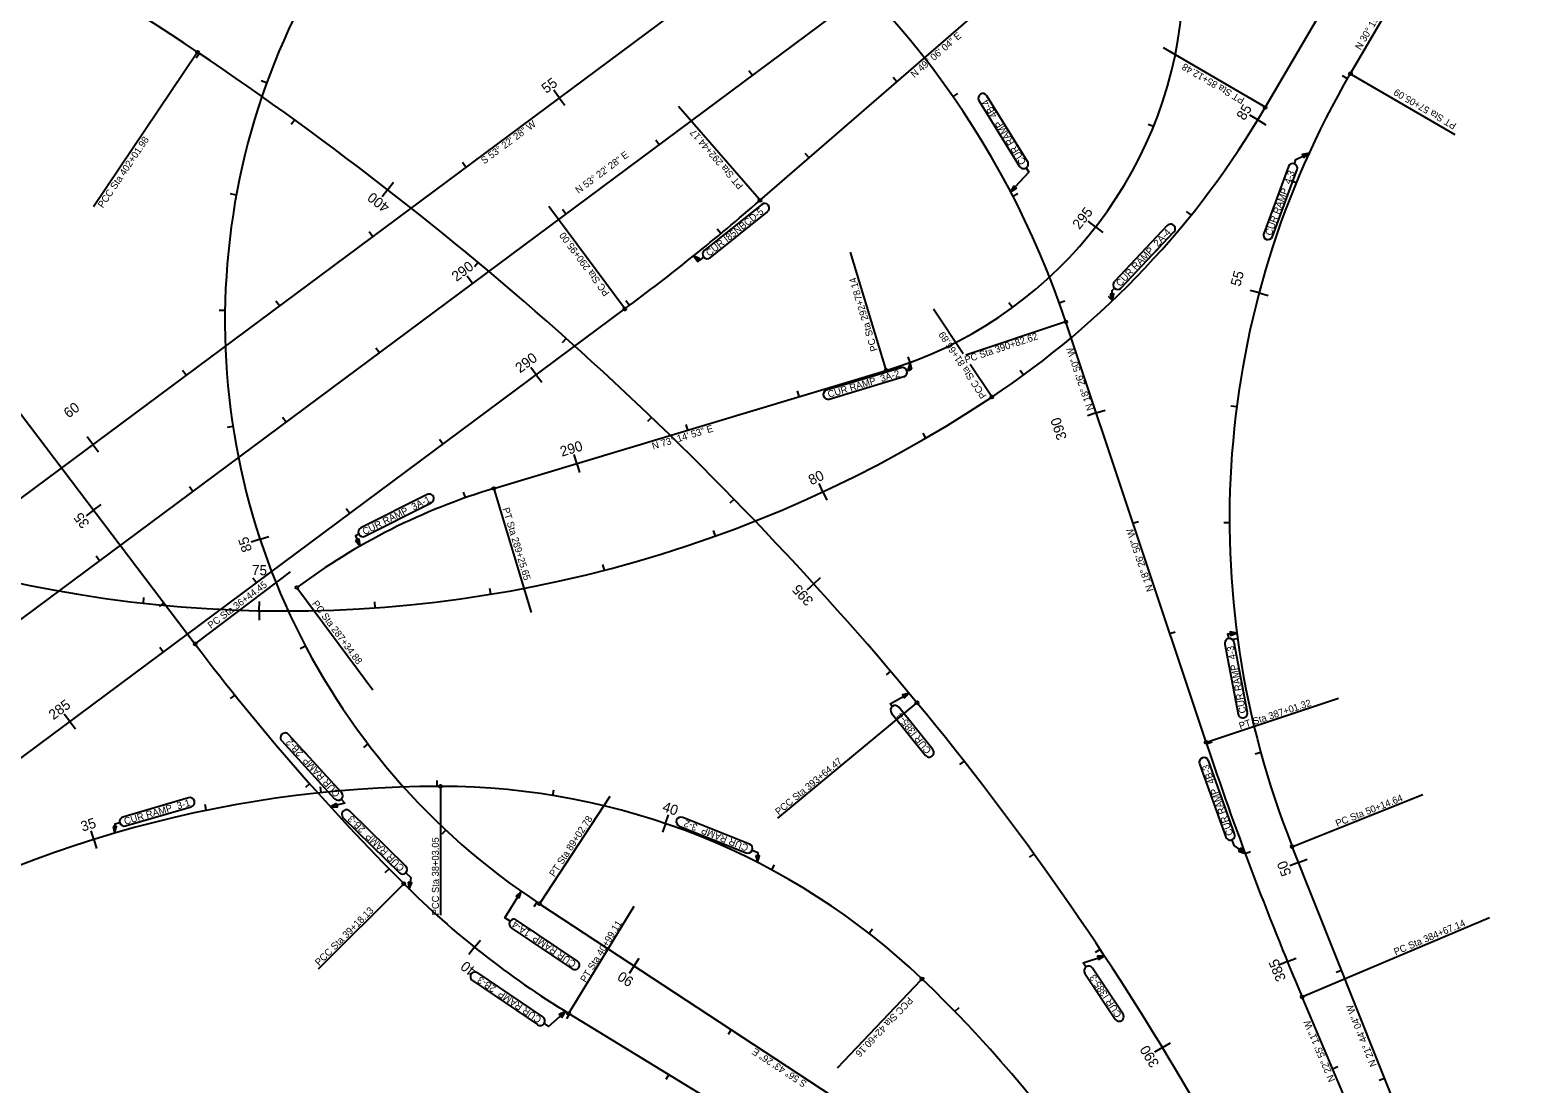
# Model space of a CAD drawing. Extents: x 1603540 to 1622629, y 1083934 to 1103503.
# Drawn here: x 1610388 to 1611685, y 1093197 to 1094104 of the extents above; entities that cross this region are included whole.
import ezdxf

# ---------------------------------------------------------------- set-up
doc = ezdxf.new("R2010")
doc.units = 0
for name, color, linetype in [('RD_EX_BldgChurch', 7, 'Continuous'), ('RD_EX_Fence_ChLk', 7, 'Continuous'), ('RD_EX_H2O', 7, 'Continuous'), ('RD_EX_Misc', 7, 'Continuous'), ('RD_HC_CL', 7, 'Continuous'), ('RD_PG_GR', 7, 'Continuous')]:
    doc.layers.add(name, color=color, linetype=linetype)

msp = doc.modelspace()

# ---------------------------------------------------------------- linework, layer by layer
at = {"layer": 'RD_EX_BldgChurch'}
for p, q in [((1610531.3, 1094083.8), (1610442.6, 1093951.6)), ((1611449.7, 1094037.9), (1611363.1, 1094088.5)), ((1611525, 1094065.7), (1611613.8, 1094013.8)), ((1611015.2, 1093958.2), (1610946, 1094038.1)), ((1610899, 1093864.9), (1610834.3, 1093951.9)), ((1611124.2, 1093812.2), (1611094, 1093912.6)), ((1611190.8, 1093825.3), (1611165.2, 1093863.8)), ((1611278, 1093852.4), (1611193.1, 1093824)), ((1611214.9, 1093789.1), (1611196.9, 1093816.1)), ((1610787.4, 1093708.2), (1610819.2, 1093602.6)), ((1610530.8, 1093576.3), (1610612, 1093637.8)), ((1610618.2, 1093623.2), (1610682.9, 1093536.2)), ((1611401, 1093491.4), (1611513.8, 1093529.1)), ((1611150.1, 1093524.3), (1611031.2, 1093425.7)), ((1610741.2, 1093451.8), (1610741.2, 1093342.2)), ((1610827, 1093353.1), (1610887.2, 1093444.7)), ((1611475.2, 1093401.7), (1611586.3, 1093446)), ((1610636.1, 1093296), (1610708.6, 1093368.5)), ((1610852.1, 1093258.8), (1610907.6, 1093350)), ((1611483.6, 1093272.5), (1611643.7, 1093340.2)), ((1611154.5, 1093286.5), (1611082.3, 1093210.7))]:
    msp.add_line(p, q, dxfattribs=at)
for centre in [(1610532, 1094084.8), (1611524, 1094066.3), (1611450.7, 1094037.2), (1611016, 1093957.2), (1610899.7, 1093863.9), (1611279.1, 1093852.8), (1611124.6, 1093811), (1611215.6, 1093788.1), (1610787.1, 1093709.4), (1610617.5, 1093624.2), (1610529.9, 1093575.5), (1611151.1, 1093525.1), (1611399.8, 1093491), (1610741.2, 1093453.1), (1611474, 1093401.3), (1610709.5, 1093369.4), (1610826.4, 1093352.1), (1611155.4, 1093287.4), (1611482.5, 1093272), (1610851.4, 1093257.7)]:
    msp.add_circle(centre, 1.25, dxfattribs=at)
at = {"layer": 'RD_EX_H2O'}
for p, q in [((1610533.6, 1094083.7), (1610530.9, 1094079.6)), ((1610591.5, 1094058.3), (1610586.8, 1094060)), ((1611009.5, 1094064.8), (1611006.5, 1094068.8)), ((1611133.8, 1094059.3), (1611130.5, 1094063)), ((1611521.4, 1094061.9), (1611517.1, 1094064.4)), ((1610843.2, 1094045.5), (1610838.5, 1094052)), ((1610843.2, 1094045.5), (1610848, 1094039.1)), ((1611182, 1094046.4), (1611186.1, 1094049.2)), ((1610615.7, 1094026.5), (1610612.7, 1094022.5)), ((1611354.6, 1094020.8), (1611349.9, 1094022.6)), ((1611444.4, 1094026.5), (1611437.5, 1094030.6)), ((1611444.4, 1094026.5), (1611451.2, 1094022.3)), ((1610929.2, 1094005.1), (1610926.3, 1094009.1)), ((1611058.2, 1093993.8), (1611054.9, 1093997.6)), ((1610763, 1093985.9), (1610760, 1093989.9)), ((1610695.7, 1093966.5), (1610690.8, 1093960.2)), ((1610695.7, 1093966.5), (1610700.6, 1093972.8)), ((1611477.3, 1093972.3), (1611472.7, 1093974.2)), ((1610565.4, 1093961.8), (1610560.5, 1093962.8)), ((1611233.6, 1093960.8), (1611238, 1093963.1)), ((1610849, 1093945.5), (1610846, 1093949.5)), ((1611387, 1093944.7), (1611383.1, 1093947.8)), ((1610682.7, 1093926.2), (1610679.7, 1093930.2)), ((1610982.3, 1093928.7), (1610979.1, 1093932.5)), ((1611304.8, 1093934.4), (1611298.5, 1093939.3)), ((1611304.8, 1093934.4), (1611311.1, 1093929.5)), ((1610773.6, 1093903.8), (1610770.4, 1093900)), ((1610768.7, 1093885.8), (1610764, 1093892.2)), ((1611445.4, 1093877.6), (1611437.7, 1093879.6)), ((1611445.4, 1093877.6), (1611453.2, 1093875.5)), ((1610602.5, 1093866.6), (1610599.5, 1093870.6)), ((1610903.7, 1093866.9), (1610900.7, 1093870.9)), ((1611233.2, 1093865), (1611230.2, 1093869.1)), ((1611273.5, 1093869.2), (1611278.2, 1093870.9)), ((1611319.4, 1093871.1), (1611315.9, 1093874.7)), ((1610555.6, 1093862.4), (1610550.6, 1093862.5)), ((1610849.3, 1093838.5), (1610845.9, 1093834.8)), ((1610688.5, 1093826.1), (1610685.5, 1093830.2)), ((1610522.2, 1093806.9), (1610519.2, 1093810.9)), ((1610823.5, 1093807.2), (1610818.7, 1093813.6)), ((1611145.3, 1093817.9), (1611143.6, 1093822.6)), ((1611242.7, 1093807), (1611239.8, 1093811)), ((1610823.5, 1093807.2), (1610828.2, 1093800.8)), ((1611049.8, 1093788.5), (1611048.3, 1093793.3)), ((1611305.3, 1093774.4), (1611297.7, 1093771.8)), ((1611305.3, 1093774.4), (1611312.9, 1093776.9)), ((1611426.2, 1093779.5), (1611421.2, 1093780.1)), ((1610562.5, 1093762.8), (1610557.5, 1093762)), ((1610608.2, 1093766.5), (1610605.2, 1093770.5)), ((1610922.7, 1093770.6), (1610919.2, 1093767)), ((1610954, 1093759.7), (1610952.6, 1093764.5)), ((1610442, 1093747.3), (1610437.2, 1093753.7)), ((1610442, 1093747.3), (1610446.7, 1093740.8)), ((1610743.2, 1093747.5), (1610740.2, 1093751.5)), ((1611158.8, 1093752.7), (1611156.3, 1093757.1)), ((1610858.3, 1093730.8), (1610856, 1093738.5)), ((1610858.3, 1093730.8), (1610860.6, 1093723.2)), ((1610528, 1093706.8), (1610525, 1093710.8)), ((1611070.1, 1093706.5), (1611066.8, 1093713.8)), ((1610442.6, 1093690.7), (1610449, 1093695.5)), ((1610762.7, 1093701.5), (1610761, 1093706.2)), ((1610993.7, 1093700.2), (1610990.1, 1093696.7)), ((1611070.1, 1093706.5), (1611073.5, 1093699.3)), ((1610442.6, 1093690.7), (1610436.2, 1093685.8)), ((1610663, 1093687.9), (1610660, 1093691.9)), ((1611336.9, 1093679.5), (1611341.7, 1093681.1)), ((1610585.8, 1093665.7), (1610593.4, 1093668.2)), ((1610977.7, 1093668.5), (1610976, 1093673.2)), ((1611420, 1093679.8), (1611415, 1093679.7)), ((1610585.8, 1093665.7), (1610578.2, 1093663.2)), ((1610671.9, 1093659.8), (1610669.4, 1093664.2)), ((1610447.7, 1093647.2), (1610444.7, 1093651.2)), ((1610882.1, 1093639.1), (1610880.9, 1093643.9)), ((1610582.7, 1093628.2), (1610579.7, 1093632.2)), ((1611062.2, 1093627.4), (1611068.2, 1093632.8)), ((1610784.3, 1093618.5), (1610783.5, 1093623.4)), ((1611062.2, 1093627.4), (1611056.3, 1093622)), ((1610485.4, 1093610.7), (1610485.9, 1093615.6)), ((1610503, 1093611), (1610499, 1093607.9)), ((1610585.1, 1093604.2), (1610585, 1093596.2)), ((1610585.1, 1093604.2), (1610585.3, 1093612.2)), ((1610685, 1093606.8), (1610684.7, 1093611.8)), ((1611368.6, 1093584.6), (1611373.3, 1093586.2)), ((1611427, 1093580.1), (1611422, 1093579.4)), ((1610502.5, 1093568.6), (1610499.5, 1093572.6)), ((1610624.9, 1093573.7), (1610620.4, 1093571.4)), ((1611128.3, 1093552.3), (1611124.5, 1093549.1)), ((1610564, 1093531.7), (1610560.1, 1093528.6)), ((1610422.2, 1093508.9), (1610417.4, 1093515.3)), ((1610422.2, 1093508.9), (1610427, 1093502.5)), ((1610678.7, 1093489.6), (1610674.7, 1093486.5)), ((1611400.2, 1093489.8), (1611405, 1093491.4)), ((1611191.6, 1093474.9), (1611187.6, 1093471.8)), ((1611447, 1093482.2), (1611442.1, 1093480.8)), ((1610628.5, 1093455.3), (1610624.8, 1093452)), ((1610638.3, 1093447.7), (1610637.8, 1093452.7)), ((1610738.1, 1093453.1), (1610738.1, 1093458.1)), ((1610837.7, 1093445.3), (1610838.5, 1093450.2)), ((1610539.5, 1093432.5), (1610538.5, 1093437.4)), ((1610934.6, 1093421.1), (1610937.2, 1093428.7)), ((1610442.7, 1093407.4), (1610440.4, 1093415)), ((1610745.7, 1093415.5), (1610742.3, 1093411.9)), ((1610934.6, 1093421.1), (1610932, 1093413.6)), ((1610442.7, 1093407.4), (1610445.1, 1093399.8)), ((1611433.5, 1093395.5), (1611438.2, 1093397.2)), ((1611026.2, 1093381.2), (1611028.5, 1093385.6)), ((1611251.8, 1093395.1), (1611247.7, 1093392.1)), ((1611479.5, 1093387.7), (1611472, 1093384.7)), ((1611479.5, 1093387.7), (1611486.9, 1093390.6)), ((1610696.8, 1093382.2), (1610693.2, 1093378.7)), ((1610824, 1093353.6), (1610821.3, 1093349.4)), ((1610770.4, 1093314.7), (1610775.4, 1093320.9)), ((1611109.8, 1093326.7), (1611112.9, 1093330.6)), ((1610770.4, 1093314.7), (1610765.4, 1093308.5)), ((1610907.6, 1093298.7), (1610912, 1093305.4)), ((1611308.7, 1093312.9), (1611304.5, 1093310.1)), ((1611469.9, 1093302.3), (1611477.3, 1093305.4)), ((1610907.6, 1093298.7), (1610903.3, 1093292)), ((1611469.9, 1093302.3), (1611462.5, 1093299.3)), ((1611516.5, 1093294.8), (1611511.9, 1093292.9)), ((1610852.2, 1093257.3), (1610849.6, 1093253)), ((1611183.7, 1093259.4), (1611187.3, 1093262.9)), ((1610991.2, 1093243.8), (1610988.5, 1093239.7)), ((1611362.3, 1093228.5), (1611355.5, 1093224.3)), ((1611362.3, 1093228.5), (1611369.2, 1093232.6)), ((1610937.6, 1093205.2), (1610935, 1093201)), ((1611508.6, 1093210.2), (1611513.2, 1093212.1)), ((1611553.5, 1093201.9), (1611548.9, 1093200))]:
    msp.add_line(p, q, dxfattribs=at)
at = {"layer": 'RD_HC_CL'}
for p, q in [((1609261, 1092765), (1614429, 1096606.7)), ((1611290.5, 1094378), (1610191.6, 1093561.1)), ((1611450.7, 1094037.2), (1611579.5, 1094257.5)), ((1611016, 1093957.2), (1611326.7, 1094226.4)), ((1611524, 1094066.3), (1611621.4, 1094233)), ((1610217, 1093988.4), (1610529.9, 1093575.5)), ((1609780.9, 1093032.2), (1610899.7, 1093863.9)), ((1611399.8, 1093491), (1611279.1, 1093852.8)), ((1610787.1, 1093709.4), (1611124.6, 1093811)), ((1611582.6, 1093128.9), (1611474, 1093401.3)), ((1610826.4, 1093352.1), (1611228.3, 1093088.3)), ((1611548.7, 1093115.4), (1611482.5, 1093272)), ((1610851.4, 1093257.7), (1611167.1, 1093065.3))]:
    msp.add_line(p, q, dxfattribs=at)
for centre, radius, start, end in [((1611155.6, 1093853.7), 600, 109.8521, 236.724), ((1609417.4, 1092424.2), 2000, 56.1301, 81.5065), ((1610558.2, 1093612.3), 760, 18.4471, 165.9491), ((1611020.8, 1094155.7), 360, 286.7519, 354.6184), ((1608910.9, 1091669.6), 2908.8, 39.6334, 56.1301), ((1612180, 1093682.7), 760, 149.6819, 201.7343), ((1610794.7, 1094420.9), 760, 303.6278, 329.6819), ((1609706.6, 1095469), 2000, 306.6256, 310.899), ((1610606.4, 1094704), 1100, 229.4294, 303.6278), ((1610945.6, 1093182.8), 550, 106.7519, 126.6256), ((1612124, 1094783.4), 2000, 217.1508, 224.9911), ((1609225.7, 1091930.4), 2500, 20.7167, 39.6334), ((1614245.6, 1094440.3), 3000, 198.4471, 202.9196), ((1610741.6, 1092453.1), 1000, 90.0249, 122.6256), ((1610741.4, 1092853.1), 600, 46.3737, 90.0249), ((1611247, 1093906.7), 760, 224.9911, 238.635), ((1610396.4, 1092491.2), 1100, 23.0073, 46.3737)]:
    msp.add_arc(centre, radius, start, end, dxfattribs=at)
at = {"layer": 'RD_PG_GR'}
for p, q in [((1611246.2, 1093990.7), (1611211.2, 1094047.3)), ((1611204.4, 1094043.1), (1611239.4, 1093986.5)), ((1611470.7, 1093986.4), (1611449.4, 1093928.9)), ((1611456.9, 1093926.1), (1611478.2, 1093983.7)), ((1611017.5, 1093953.8), (1610968.1, 1093914.1)), ((1610973.1, 1093907.9), (1611022.5, 1093947.5)), ((1611366.4, 1093935.6), (1611320.9, 1093887.4)), ((1611326.7, 1093881.9), (1611372.2, 1093930.1)), ((1611137.4, 1093813.3), (1611073.3, 1093794)), ((1611075.6, 1093786.3), (1611139.7, 1093805.6)), ((1610729.6, 1093704.2), (1610672.5, 1093675.5)), ((1610676.1, 1093668.3), (1610733.2, 1093697)), ((1611416.1, 1093575.5), (1611427.5, 1093515.2)), ((1611435.4, 1093516.7), (1611424, 1093577)), ((1611129.2, 1093516.2), (1611158.4, 1093479.7)), ((1611164.6, 1093484.7), (1611135.4, 1093521.2)), ((1610604.5, 1093492.4), (1610650, 1093442.4)), ((1610655.9, 1093447.8), (1610610.4, 1093497.8)), ((1611424.4, 1093412.2), (1611401.8, 1093475.3)), ((1611394.3, 1093472.6), (1611416.9, 1093409.5)), ((1610524.4, 1093443.3), (1610467.9, 1093426.7)), ((1610470.1, 1093419.1), (1610526.7, 1093435.6)), ((1610657.4, 1093426.1), (1610705.7, 1093378.7)), ((1610711.3, 1093384.4), (1610663, 1093431.8)), ((1611007, 1093403.4), (1610949.5, 1093426.4)), ((1610946.5, 1093419), (1611004.1, 1093396)), ((1610802, 1093331.5), (1610854.4, 1093296)), ((1610858.9, 1093302.7), (1610806.5, 1093338.1)), ((1610829.2, 1093254.7), (1610773.1, 1093292.6)), ((1611295.4, 1093292.2), (1611321.7, 1093252.8)), ((1611328.4, 1093257.2), (1611302.1, 1093296.7)), ((1610768.6, 1093286), (1610824.7, 1093248.1))]:
    msp.add_line(p, q, dxfattribs=at)
for points in [[(1611475.8, 1093988.8), (1611477.1, 1093992.3), (1611488.4, 1093997.8)], [(1611244.9, 1093985.2), (1611247.2, 1093981.5), (1611231.6, 1093964.5)], [(1610967.4, 1093908.5), (1610963.8, 1093905.5), (1610958.7, 1093909.5)], [(1611321.1, 1093881.7), (1611318.7, 1093879.3), (1611319.4, 1093871.1)], [(1611142.4, 1093810.6), (1611145.1, 1093811.4), (1611145.3, 1093817.9)], [(1610670.7, 1093670.1), (1610667.9, 1093668.7), (1610671.9, 1093659.8)], [(1611419.3, 1093580.2), (1611418.5, 1093584.3), (1611426.4, 1093584.8)], [(1611129.8, 1093521.8), (1611127.9, 1093524.1), (1611144.5, 1093533.2)], [(1610655.7, 1093442.2), (1610658.8, 1093438.8), (1610646.5, 1093435.6)], [(1610465.2, 1093421.8), (1610461, 1093420.5), (1610460.5, 1093412.8)], [(1611009.3, 1093398.2), (1611014.2, 1093396.3), (1611013.8, 1093387.7)], [(1611422, 1093407.1), (1611423.7, 1093402.2), (1611433.5, 1093395.5)], [(1610711.3, 1093378.7), (1610715.5, 1093374.7), (1610714.1, 1093364.6)], [(1610801, 1093337), (1610796.5, 1093340.1), (1610810.5, 1093362.7)], [(1611296.5, 1093297.8), (1611294.2, 1093301.3), (1611312.3, 1093307.4)], [(1610830.2, 1093249.1), (1610834.1, 1093246.5), (1610848.7, 1093259.4)]]:
    msp.add_lwpolyline(points, dxfattribs=at)
for points in [[(1611483.9, 1093993.9), (1611488.4, 1093997.8), (1611482.5, 1093996.7)], [(1611234.4, 1093969.8), (1611231.6, 1093964.5), (1611236.7, 1093967.7)], [(1610964.3, 1093907.1), (1610958.7, 1093909.5), (1610962.4, 1093904.7)], [(1611317.4, 1093876.7), (1611319.4, 1093871.1), (1611320.5, 1093877)], [(1611146.7, 1093812.1), (1611145.3, 1093817.9), (1611143.6, 1093812.2)], [(1610668.1, 1093664.5), (1610671.9, 1093659.8), (1610671, 1093665.8)], [(1611420.7, 1093582.9), (1611426.4, 1093584.8), (1611420.5, 1093586)], [(1611140.2, 1093529.1), (1611144.5, 1093533.2), (1611138.7, 1093531.8)], [(1610651.7, 1093438.5), (1610646.5, 1093435.6), (1610652.5, 1093435.5)], [(1610459.3, 1093418.6), (1610460.5, 1093412.8), (1610462.4, 1093418.5)], [(1611427.8, 1093397.5), (1611433.5, 1093395.5), (1611429.6, 1093400)], [(1611012.5, 1093393.5), (1611013.8, 1093387.7), (1611015.6, 1093393.4)], [(1610713.4, 1093370.6), (1610714.1, 1093364.6), (1610716.4, 1093370.2)], [(1610808.8, 1093357), (1610810.5, 1093362.7), (1610806.1, 1093358.6)], [(1611307.3, 1093304.1), (1611312.3, 1093307.4), (1611306.3, 1093307)], [(1610845.4, 1093254.4), (1610848.7, 1093259.4), (1610843.3, 1093256.7)]]:
    msp.add_lwpolyline(points, close=True, dxfattribs=at)
for centre, start, end in [((1611207.8, 1094045.2), 31.726, 211.726), ((1611242.8, 1093988.6), 211.726, 31.726), ((1611474.4, 1093985), 339.726, 159.726), ((1611020, 1093950.7), 308.7623, 128.7623), ((1611369.3, 1093932.8), 316.6549, 136.6549), ((1611453.1, 1093927.5), 159.726, 339.726), ((1610970.6, 1093911), 128.7623, 308.7623), ((1611323.8, 1093884.6), 136.6549, 316.6549), ((1611138.6, 1093809.4), 286.726, 106.726), ((1611074.4, 1093790.2), 106.726, 286.726), ((1610731.4, 1093700.6), 296.6888, 116.6888), ((1610674.3, 1093671.9), 116.6888, 296.6888), ((1611420, 1093576.3), 10.6915, 190.6915), ((1611132.3, 1093518.7), 38.6915, 218.6915), ((1611431.4, 1093516), 190.6915, 10.6915), ((1610607.4, 1093495.1), 42.3719, 222.3719), ((1611161.5, 1093482.2), 218.6915, 38.6915), ((1611398, 1093474), 19.6915, 199.6915), ((1610653, 1093445.1), 222.3719, 42.3719), ((1610525.5, 1093439.5), 286.3252, 106.3252), ((1610469, 1093422.9), 106.3252, 286.3252), ((1610660.2, 1093429), 45.4891, 225.4891), ((1610948, 1093422.7), 68.1993, 248.1993), ((1611420.6, 1093410.9), 199.6915, 19.6915), ((1611005.5, 1093399.7), 248.1993, 68.1993), ((1610708.5, 1093381.5), 225.4891, 45.4891), ((1610804.3, 1093334.8), 55.9145, 235.9145), ((1610770.8, 1093289.3), 55.9145, 235.9145), ((1610856.7, 1093299.4), 235.9145, 55.9145), ((1611298.8, 1093294.4), 33.6915, 213.6915), ((1610826.9, 1093251.4), 235.9145, 55.9145), ((1611325, 1093255), 213.6915, 33.6915)]:
    msp.add_arc(centre, 4, start, end, dxfattribs=at)

# ---------------------------------------------------------------- texts
at = {"layer": 'RD_EX_BldgChurch'}
for s, rotation, p in [('PT Sta 85+12.48', 149.6819, (1611433.5, 1094045)), ('PT Sta 57+05.09', 149.6819, (1611615.8, 1094023.1)), ('PCC Sta 402+01.98', 56.1301, (1610450.7, 1093950.2)), ('PT Sta 292+44.17', 130.899, (1611002.2, 1093970.1)), ('PC Sta 290+95.00', 126.6256, (1610886.9, 1093877.7)), ('PC Sta 292+78.14', 106.7519, (1611117.3, 1093828.4)), ('PCC Sta 81+66.89', 123.6278, (1611211.3, 1093789.2)), ('PC Sta 390+82.62', 18.4471, (1611193.2, 1093817.1)), ('PT Sta 289+25.65', 286.7519, (1610794.4, 1093692)), ('PC Sta 36+44.45', 37.1508, (1610543.6, 1093588.4)), ('PC Sta 287+34.88', 306.6256, (1610630.3, 1093610.3)), ('PT Sta 387+01.32', 18.4471, (1611429.3, 1093502)), ('PCC Sta 393+64.47', 39.6334, (1611032.1, 1093428.1)), ('PC Sta 50+14.64', 21.7343, (1611512.7, 1093418.2)), ('PT Sta 89+02.78', 56.724, (1610839.1, 1093374.8)), ('PCC Sta 38+03.05', 90.0249, (1610739.7, 1093342.2)), ('PCC Sta 39+18.13', 44.9911, (1610636.6, 1093298.3)), ('PT Sta 40+99.11', 58.635, (1610866, 1093283.9)), ('PC Sta 384+67.14', 22.9196, (1611562.9, 1093307.7)), ('PCC Sta 42+60.16', 226.3737, (1611143.9, 1093272.4))]:
    msp.add_text(s, height=6, rotation=rotation, dxfattribs=at).set_placement(p)
at = {"layer": 'RD_EX_Fence_ChLk'}
for s, rotation, p in [('N 30%%d 19\' 05" E', 59.6819, (1611532.8, 1094086.2)), ('N 49%%d 06\' 04" E', 40.899, (1611148.8, 1094062.4)), ('S 53%%d 22\' 28" W', 36.6256, (1610778.7, 1093988.2)), ('N 53%%d 22\' 28" E', 36.6256, (1610859.9, 1093962.8)), ('N 18%%d 26\' 50" W', 108.4471, (1611303.1, 1093777.6)), ('N 73%%d 14\' 53" E', 16.7519, (1610924.1, 1093742.8)), ('N 18%%d 26\' 50" W', 108.4471, (1611354.7, 1093621.8)), ('N 21%%d 44\' 04" W', 111.7343, (1611546.8, 1093213.3)), ('N 22%%d 55\' 11" W', 112.9196, (1611511.1, 1093200.4)), ('S 56%%d 43\' 26" E', 146.724, (1611056.8, 1093198.7))]:
    msp.add_text(s, height=6, rotation=rotation, dxfattribs=at).set_placement(p)
at = {"layer": 'RD_EX_Misc'}
for s, rotation, p in [('55', 36.6256, (1610832.1, 1094048.8)), ('85', 58.7409, (1611432.9, 1094025.4)), ('400', 142.1517, (1610698.1, 1093952.9)), ('295', 52.0627, (1611290.9, 1093931.7)), ('290', 36.6256, (1610754.8, 1093887)), ('55', 75.1435, (1611429.2, 1093882.7)), ('290', 36.6256, (1610809.5, 1093808.3)), ('60', 36.6256, (1610421, 1093769.5)), ('390', 108.4471, (1611280.2, 1093752.8)), ('290', 16.7519, (1610845.5, 1093736.7)), ('80', 24.9351, (1611060.2, 1093712.1)), ('35', 127.1508, (1610439.6, 1093679.3)), ('85', 108.2612, (1610579.1, 1093656.3)), ('75', 358.8916, (1610578.8, 1093634.9)), ('395', 132.303, (1611062.6, 1093613.3)), ('285', 36.6256, (1610408, 1093509.9)), ('40', 341.2171, (1610931.4, 1093432)), ('35', 17.3881, (1610433.1, 1093414.1)), ('50', 111.7343, (1611473.4, 1093377.9)), ('40', 141.1632, (1610773.1, 1093295.3)), ('90', 146.724, (1610908.1, 1093287.4)), ('385', 112.292, (1611468.8, 1093287.4)), ('390', 121.2804, (1611359.9, 1093214.6))]:
    msp.add_text(s, height=8.75, rotation=rotation, dxfattribs=at).set_placement(p)
at = {"layer": 'RD_PG_GR'}
for s, rotation, p in [('CUR RAMP_4B-4', 121.726, (1611245.3, 1093990.2)), ('CUR RAMP_4-3', 69.726, (1611456, 1093926.4)), ('CUR I85NBCD-5', 38.7623, (1610972.4, 1093908.7)), ('CUR RAMP_2A-4', 46.6549, (1611326, 1093882.6)), ('CUR RAMP_3A-2', 16.726, (1611075.3, 1093787.3)), ('CUR RAMP_3A-1', 26.6888, (1610675.7, 1093669.2)), ('CUR RAMP_4-3', 100.6915, (1611434.4, 1093516.5)), ('CUR I385-4', 128.6915, (1611163.8, 1093484.1)), ('CUR RAMP_2B-2', 132.3719, (1610655.2, 1093447.2)), ('CUR RAMP_4B-3', 109.6915, (1611423.4, 1093411.9)), ('CUR RAMP_3-1', 16.3252, (1610469.8, 1093420)), ('CUR RAMP_2B-3', 135.4891, (1610710.6, 1093383.6)), ('CUR RAMP_3-2', 158.1993, (1611006.7, 1093402.5)), ('CUR RAMP_1A-4', 145.9145, (1610858.4, 1093301.8)), ('CUR RAMP_2B-3', 145.9145, (1610828.6, 1093253.9)), ('CUR I385-3', 123.6915, (1611327.5, 1093256.7))]:
    msp.add_text(s, height=6, rotation=rotation, dxfattribs=at).set_placement(p)

doc.saveas('drawing.dxf')
